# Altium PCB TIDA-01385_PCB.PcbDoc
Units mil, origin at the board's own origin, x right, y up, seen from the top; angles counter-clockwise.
Board outline 2300 x 1400 mil, 2 copper layers (Top Layer, Bottom Layer), stack 62 mil thick; 51 components, 23 nets, 141 pads, 23 vias.
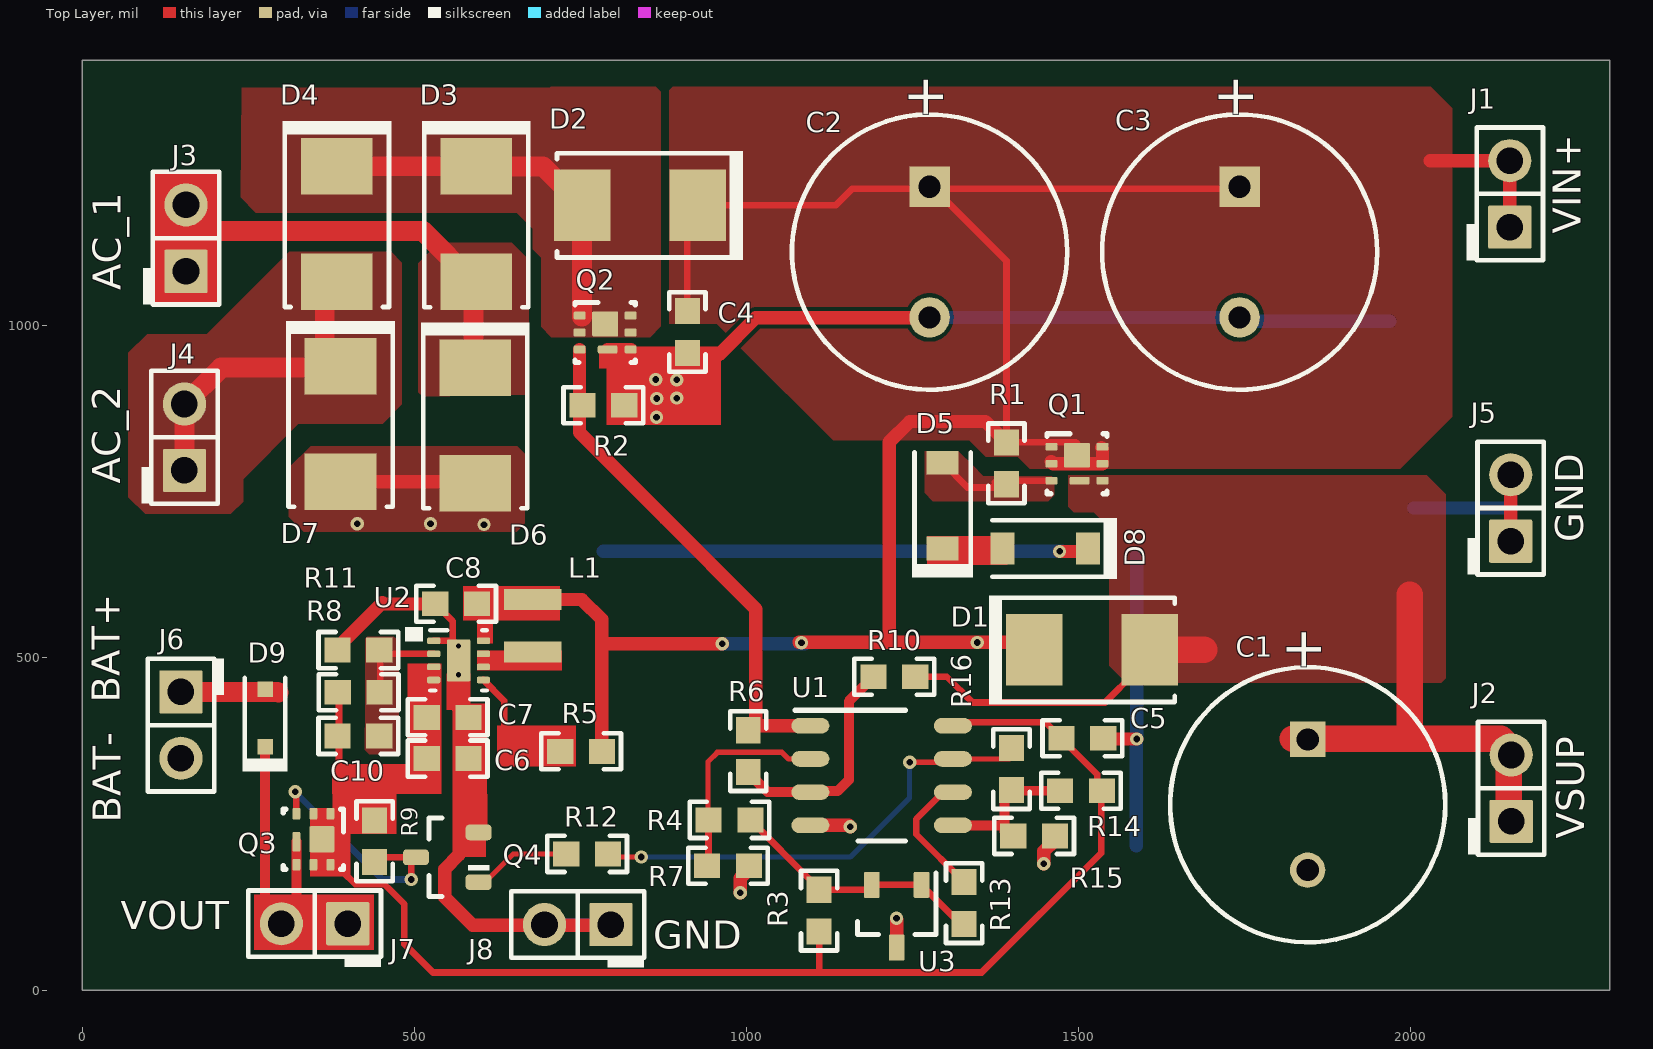
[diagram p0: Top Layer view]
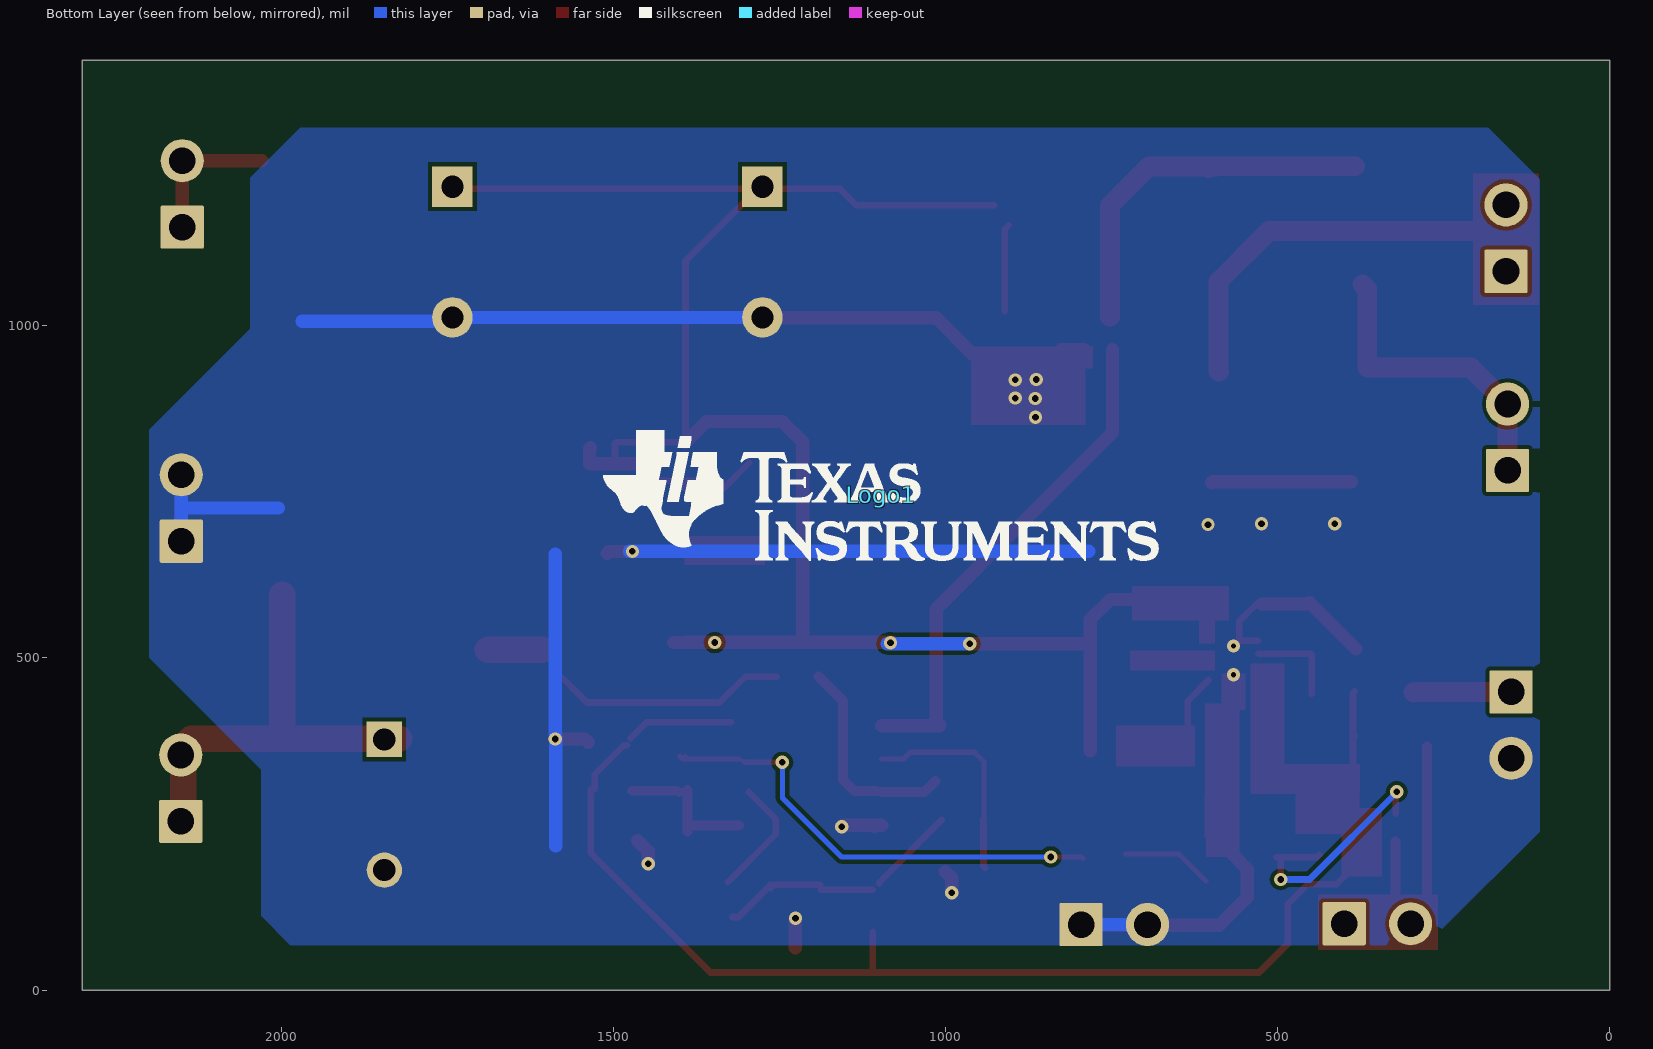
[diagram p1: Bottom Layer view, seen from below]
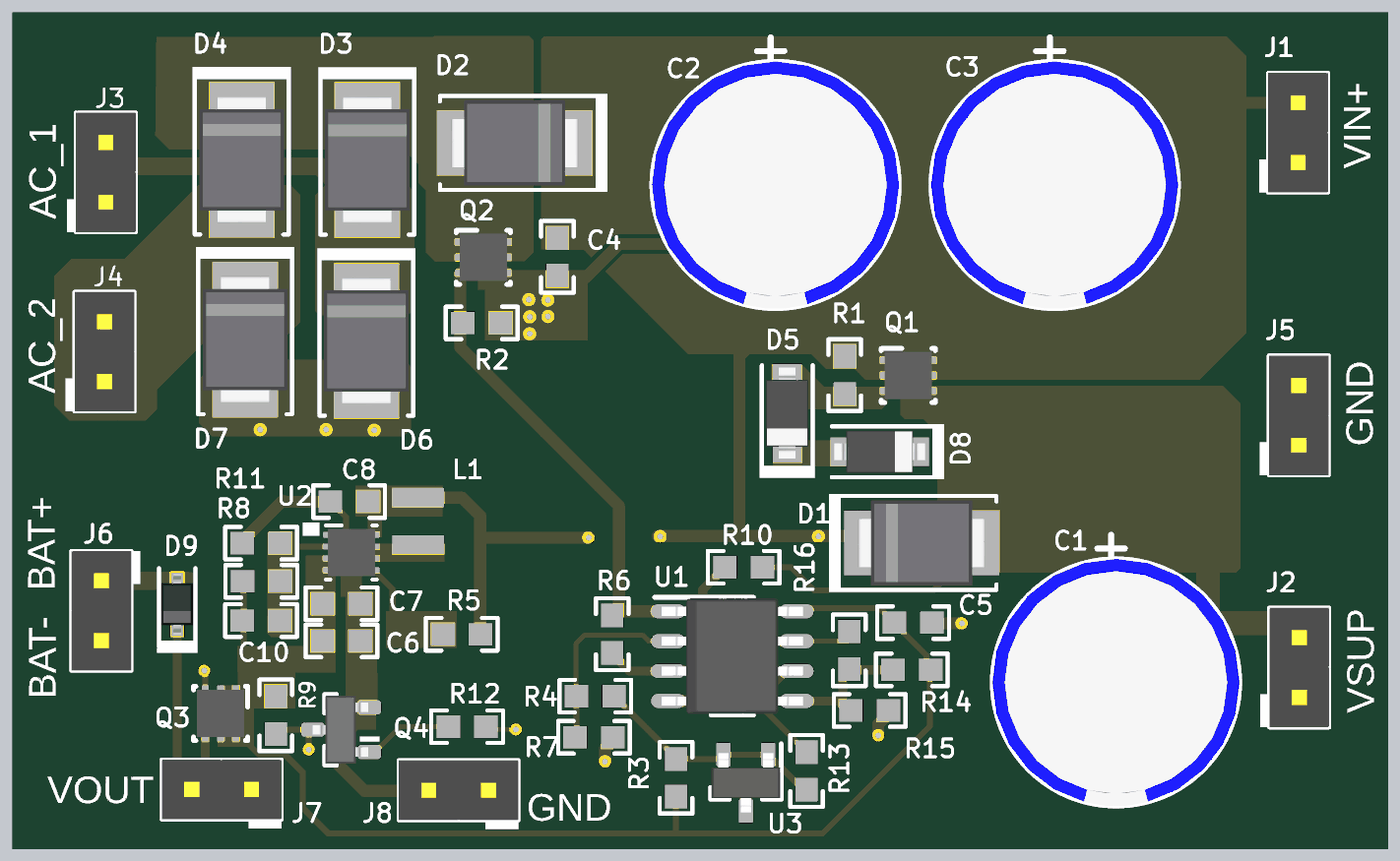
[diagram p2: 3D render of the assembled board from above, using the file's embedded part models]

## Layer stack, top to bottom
Top Solder: solder mask 0.4, Solder Resist, Dk 3.5
Top Layer: signal copper 1.4
Dielectric1: core 59.2, FR-4, Dk 4.8
Bottom Layer: signal copper 1.4
Bottom Solder: solder mask 0.4, Solder Resist, Dk 3.5

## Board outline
0,0 2300,0 2300,1400 0,1400

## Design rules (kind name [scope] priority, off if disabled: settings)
AcuteAngle [All] p1: minimum=4.50000000000000E+0001 checktracksonly=FALSE
AssemblyTestPointUsage [All] p1: valid=2
Clearance "U1 Clearance" [InComponent('Q1','Q2','Q3')] p1: gap=3.5
Clearance "U2 Clearance" [InComponent('U2')] p2: gap=4
Clearance Clearance_BoardEdge_MountingHoles [OnCopper and InComponentClass('Mounting Holes') vs IsKeepOut] p3: gap=3.94
Clearance Clearance_BoardEdge_Poly [OnCopper and InPoly vs IsKeepOut] p4: gap=10
Clearance Clearance_BoardEdge [OnCopper and Not InComponentClass('Logo') and not InComponentClass('FiducialMark') and not InRegion(1000,500,4000,800) vs IsKeepOut] p5: gap=30
Clearance [All] p6: gap=6
ComponentClearance ComponentClearance_SHUNT [InComponentClass('Shunt')] p1: gap=0 collisioncheckmode=3 verticalgap=0 showdistances=FALSE
ComponentClearance ComponentClearance_Logo [All] p2: gap=10 collisioncheckmode=3 verticalgap=10 showdistances=FALSE
ComponentClearance ComponentClearance_ScrewToNut [(HasFootprint('NY PMS 440 0025 PH')) vs (HasFootprint('Keystone_1902C'))] p3: gap=5 collisioncheckmode=3 verticalgap=10 showdistances=FALSE
ComponentClearance ComponentClearance_MountingHoles [InComponentClass('Mounting Holes')] p4: gap=250 collisioncheckmode=3 verticalgap=100000 showdistances=FALSE
ComponentClearance ComponentClearance_SmallPassives [HasFootprint('0201*') or HasFootprint('0402*') or HasFootprint('0508') or HasFootprint('0603*') or HasFootprint('0612') or HasFootprint('0805*') or HasFootprint('0815*') or HasFootprint('0830*') or HasFootprint('1206*') or HasFootprint('1210*') or HasFootprint('1808*') or HasFootprint('1812*') or HasFootprint('1825*') or HasFootprint('2010*') or HasFootprint('2220*') or HasFootprint('2225*') or HasFootprint('2512*') or HasFootprint('2728*') or HasFootprint('3518*') vs HasFootprint('0201*') or HasFootprint('0402*') or HasFootprint('0508') or HasFootprint('0603*') or HasFootprint('0612') or HasFootprint('0805*') or HasFootprint('0815*') or HasFootprint('0830*') or HasFootprint('1206*') or HasFootprint('1210*') or HasFootprint('1808*') or HasFootprint('1812*') or HasFootprint('1825*') or HasFootprint('2010*') or HasFootprint('2220*') or HasFootprint('2225*') or HasFootprint('2512*') or HasFootprint('2728*') or HasFootprint('3518*')] p5: gap=20 collisioncheckmode=3 verticalgap=10 showdistances=FALSE
ComponentClearance ComponentClearance_THtoSMT [IsThruComponent vs IsSMTComponent] p6 off: gap=10 collisioncheckmode=3 verticalgap=100000 showdistances=FALSE
ComponentClearance ComponentClearance_THtoTH [IsThruComponent vs IsThruComponent] p7: gap=10.11 collisioncheckmode=3 verticalgap=100000 showdistances=FALSE
ComponentClearance [All] p8: gap=10 collisioncheckmode=3 verticalgap=10 showdistances=FALSE
DiffPairsRouting [All] p1: maxlimit=100 minlimit=10 mostfreqgap=10 toplayer_minwidth=15 toplayer_maxwidth=15 toplayer_prefwidth=15 bottomlayer_minwidth=15 bottomlayer_maxwidth=15 bottomlayer_prefwidth=15 maxuncoupledlength=1000
FabricationTestPointUsage TestPointUsage [All] p1: valid=2 allowmultiple=FALSE
FabricationTestpoint Testpoint [All] p1: side=3 testpointundercomponent=TRUE minsize=40 maxsize=100 preferedsize=60 minholesize=0 maxholesize=40 preferedholesize=32 testpointgrid=1 allowsidetop=TRUE allowsidebottom=TRUE usegrid=TRUE gridtolerance=0.01
FanoutControl Fanout_LCC [IsLCC] p1: bgadir=Out bgaviamode=Centered fanoutstyle=Auto fanoutdirection=Alternating viagrid=1 // Fanout_LCC (Default Rule)
FanoutControl Fanout_BGA [IsBGA] p2: bgadir=Out bgaviamode=Centered fanoutstyle=Auto fanoutdirection=Alternating viagrid=1 // Fanout_BGA (Default Rule)
FanoutControl Fanout_Default [All] p4: bgadir=Out bgaviamode=Centered fanoutstyle=Auto fanoutdirection=Alternating viagrid=1 // Fanout_Default (Default Rule)
FanoutControl Fanout_Small [(CompPinCount < 5)] p5: bgadir=Out bgaviamode=Centered fanoutstyle=Auto fanoutdirection=OutThenIn viagrid=1 // Fanout_Small (Default Rule)
HoleSize [All] p1: absolutevalues=TRUE maxlimit=180 minlimit=7 maxpercent=80.000 minpercent=20.000
HoleToHoleClearance [All] p1: gap=1 allowstackedmicrovias=TRUE
MinimumAnnularRing MinimumAnnularRing_small [TouchesRoom('BGA_Room')] p1: minimumring=2.8
MinimumAnnularRing [All] p2: minimumring=5
MinimumSolderMaskSliver U2 [InComponent('U1')] p1: minsoldermaskwidth=3
MinimumSolderMaskSliver "SW PIN" [InNet('SW')] p2: minsoldermaskwidth=10
MinimumSolderMaskSliver U1 [InComponent('U2')] p3: minsoldermaskwidth=3
MinimumSolderMaskSliver SilkscreenOverComponentPads [All] p4: minsoldermaskwidth=5
MinimumSolderMaskSliver MinimumSolderMaskSliver_Logo [InComponentClass('Logo') vs InComponentClass('Logo')] p5: minsoldermaskwidth=0.7
MinimumSolderMaskSliver [All] p6: minsoldermaskwidth=4
PlaneClearance [All] p1: clearance=10
PlaneConnect [All] p1: planeconnectstyle=Direct reliefexpansion=10 reliefentries=4 reliefconductorwidth=10 reliefairgap=10
PolygonConnect PolygonConnect-TH-Relief [IsPoly vs (IsThruPin)  And Not (InComponent('U3'))  And Not (InComponent('U4'))] p1: connectstyle=Direct reliefconductorwidth=20 reliefentries=4 polygonreliefangle="90 Angle" airgapwidth=10
PolygonConnect PolygonConnect-DirectConn [All] p2: connectstyle=Direct reliefconductorwidth=10 reliefentries=4 polygonreliefangle="90 Angle" airgapwidth=10
RoutingVias [All] p1: holewidth=10 width=22 viastyle="Through Hole" minholewidth=4 minwidth=10 maxholewidth=50 maxwidth=100
SMDToCorner [All] p1: distance=0
SilkToBoardRegionClearance [Not ((IsComment or IsDesignator) And (Hide <> 'False')) and not InRegion(1000,500,4000,800)] p1:
SilkToSilkClearance "Pb Free Logo" [(HasFootprint('Pb-Free_Overlay_Medium') OR HasFootprint('Pb-Free_Overlay_Small')) vs (HasFootprint('Pb-Free_Overlay_Medium') OR HasFootprint('Pb-Free_Overlay_Small'))] p1: silktosilkclearance=0
SilkToSilkClearance [All] p2: silktosilkclearance=3
SilkToSolderMaskClearance [IsPad] p1: minsilkscreentomaskgap=4 clearancetoexposedcopper=TRUE
SolderMaskExpansion [All] p1: expansion=1
Width [All] p1: maxlimit=100 minlimit=6 preferedwidth=10 checkconnectedcopper=TRUE
13 further rules are at their usual default settings.

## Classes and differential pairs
component class Header: J1 J2 J3 J4 J5 J6 J7 J8
component class Logo: Logo1

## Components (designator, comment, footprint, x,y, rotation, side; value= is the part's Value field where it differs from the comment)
C1 "100ZL100MEFC10X23" ZL_1000x2300 1845.13,278.98 r270 top
C2 "ECA-2AHG101" NHG_1000x2000 1275.87,1111.17 r270 top
C3 "ECA-2AHG101" NHG_1000x2000 1742.66,1111.17 r270 top
C4 "GRM188R60J106ME47D" 0603 911.12,990.87 r270 top
C5 "GRM185R60J105KE26D" 0603 1505.93,378.99 r0 top
C6 "GRM188R60J226MEA0D" 0603 550.15,348.41 r0 top
C7 "GRM188R60J226MEA0D" 0603 550.15,410.56 r0 top
C8 "GRM188R60J106ME47D" 0603 563,581.61 r180 top
C10 "GRM188R61A224KA01D" 0603 415.75,382.5 r0 top
D1 "SL22-E3/52T" SMB 1520.21,512.3 r0 top
D2 "SL22-E3/52T" SMB 839.83,1181.45 r180 top
D3 "SL22-E3/52T" SMB 593.31,1153.1 r270 top
D4 "SL22-E3/52T" SMB 383.4,1153.35 r270 top
D5 "1N4148W-7-F" SOD-123 1295.58,729.38 r90 top
D6 "SL22-E3/52T" SMB 591.84,850.24 r270 top
D7 "SL22-E3/52T" SMB 389.01,852.47 r270 top
D8 "1N4148W-7-F" SOD-123 1450,664.81 r180 top
D9 "BAT54WS-7-F" SOD-323 275.45,409.8 r90 top
J1 "TSW-102-07-G-S" TSW-102-07-G-S#1 2149.42,1198.71 r90 top
J2 "TSW-102-07-G-S" TSW-102-07-G-S#1 2151.54,303.9 r90 top
J3 "TSW-102-07-G-S" TSW-102-07-G-S#2 144.05,1132.74 r90 top
J4 "TSW-102-07-G-S" TSW-102-07-G-S#1 153.97,832.32 r90 top
J5 "TSW-102-07-G-S" TSW-102-07-G-S#1 2150.81,725.76 r90 top
J6 "TSW-102-07-G-S" TSW-102-07-G-S#1 148.68,398.93 r270 top
J7 "TSW-102-07-G-S" TSW-102-07-G-S#1 349.88,99.88 r180 top
J8 "TSW-102-07-G-S" TSW-102-07-G-S#1 746.07,98.57 r180 top
L1 "74479887247" WE-PMI_1008 678.44,548.61 r270 top
Logo1 "Texas Instruments" TI_Stacked_Overlay_Small 1097.29,744.79 r180 bottom
Q1 "CSD25310Q2" DQK0006C 1497.87,792.44 r0 top
Q2 "CSD13202Q2" DQK0006C 787.25,990.02 r0 top
Q3 "CSD25310Q2" DQK0006C 348.08,227.07 r270 top
Q4 "MMBT3904" SOT-23 549.58,199.92 r180 top
R1 "CRCW0603200KFKEA" 0603 1391.57,793.07 r270 top
R2 "RC0603FR-07511KL" 0603 784.6,880.42 r180 top
R3 "CRCW060324K9FKEA" 0603 1109.48,119.45 r270 top
R4 "CRCW0603523KFKEA" 0603 974.48,256.03 r0 top
R5 "CRCW0603200KFKEA" 0603 751.15,359.41 r0 top
R6 "CRCW06031M00FKEA" 0603 1002.88,359.69 r90 top
R7 "CRCW06032M00FKEA" 0603 972.35,187.15 r180 top
R8 "CRCW06031M00FKEA" 0603 416.18,448.3 r180 top
R9 "CRCW06032M00FKEA" 0603 440.34,224.03 r90 top
R10 "RC0603FR-0769K8L" 0603 1222.66,471.77 r180 top
R11 "CRCW0603287KFKEA" 0603 415.82,511.89 r0 top
R12 "CRCW06032M00FKEA" 0603 760.2,204.93 r0 top
R13 "CRCW06031M00FKEA" 0603 1327.81,130.92 r90 top
R14 "CRCW06031M00FKEA" 0603 1503.81,300.04 r180 top
R15 "CRCW06037M50FKEA" 0603 1433.3,232.09 r180 top
R16 "CRCW06035M90FKEA" 0603 1399.23,332.67 r90 top
U1 "TLV3492AIDR" D0008A_N 1203.63,322.99 r0 top
U2 "TPS61021ADSGR" DSG0008A 566.67,496.32 r0 top
U3 "ATL431AIDBZR" DBZ0003A_N 1226.3,111.1 r270 top

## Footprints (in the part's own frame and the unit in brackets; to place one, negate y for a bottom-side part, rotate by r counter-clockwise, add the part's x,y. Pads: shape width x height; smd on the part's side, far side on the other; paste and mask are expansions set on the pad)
0603 [mm] "0603 from SM-752 data"
  rect 1x0.95 smd: 1(-0.8,0) 2(0.8,0)
  silkscreen extent -1.52,-0.69 1.52,0.69, body extent -0.87,-0.47 0.87,0.47, height 1
D0008A_N [mm] "SOIC, 8-Leads, Body 4.9x3.9mm, Pitch 1.27mm, IPC Medium Density"
  oval 1.45x0.6 smd: 1(-2.725,1.905) 2(-2.725,0.635) 3(-2.725,-0.635) 4(-2.725,-1.905) 5(2.725,-1.905) 6(2.725,-0.635) 7(2.725,0.635) 8(2.725,1.905)
  silkscreen extent -3.3,-2.5 0.9,2.5, body extent -3,-2.45 3,2.45, height 1.63
DBZ0003A_N [mm] "SOT23, 3-Leads, Body 2.9x1.3mm, Pitch 0.95mm, Lead Span 2.4mm, IPC Medium Density"
  rrect17% 1x0.6 smd: 1(-1.2,0.95) 2(-1.2,-0.95) 3(1.2,0)
  silkscreen extent -1.65,-1.5 0.7,1.5, body extent -1.26,-1.46 1.26,1.46, height 0.98
DQK0006C [mm] "WSON"
  rrect12% 0.9x0.86 on Top Paste: 0(0,0.325)
  rrect34% 0.7x0.29 on Top Paste: 0(0.095,-0.65)
  rrect33% 0.45x0.3 smd: 1(-0.975,0.65) 2(-0.975,0) 3(-0.975,-0.65) 4(0.975,-0.65) 5(0.975,0) 6(0.975,0.65)
  rrect33% 0.75x0.3 smd paste-0.15: 7(0.095,-0.65)
  rrect11% 1x0.95 smd paste-0.5: 8(0,0.325)
  silkscreen extent -1.15,-1.15 1.15,1.15, body extent -1,-1 1,1, height 0.82
DSG0008A [mm] "SON, 8-Leads, Body 2x2mm, Pitch 0.5mm, Thermal Pad 1.6x0.9mm, TI Recommended"
  rrect40% 0.5x0.25 smd: 1(-0.95,0.75) 2(-0.95,0.25) 3(-0.95,-0.25) 4(-0.95,-0.75) 5(0.95,-0.75) 6(0.95,-0.25) 7(0.95,0.25) 8(0.95,0.75)
  rrect14% 0.9x0.7 on Top Paste: 9(0,-0.45) 9(0,0.45)
  rrect11% 0.9x1.6 smd paste-0.45: 9(0,0)
  silkscreen extent -1.07,-1.15 1.07,1.15, body extent -1,-1 1,1, height 0.77
NHG_1000x2000 [mm] "PANASONIC"
  rect 1.55x1.55 hole 0.85: 1(-2.5,0)
  round 1.55 hole 0.85: 2(2.5,0)
  silkscreen extent -5.26,-5.26 5.26,5.26, body extent -5.21,-5.24 5.24,5.24, height 22.01
SMB [mil] "Molded Diode, 2-Leads, Body 5.4x3.6mm, IPC Medium Density, based on OnSemi component dimensions"
  rect 85x107.99 smd: 1(-87.01,0) 2(87.01,0)
  silkscreen extent -155,-82 125,82, body extent -106,-71 106,71, height 91
SOD-123 [mm] "On Semi recommended land pattern"
  rect 0.915x1.22 smd: 1(-1.637,0) 2(1.637,0)
  silkscreen extent -2.74,-1.17 2.03,1.17, body extent -1.93,-0.9 1.93,0.9, height 1.35
SOD-323 [mm] "NXP recommended land pattern"
  rect 0.6x0.6 smd paste-0.05: 1(-1.1,0) 2(1.1,0)
  silkscreen extent -2.06,-0.86 1.53,0.86, body extent -1.3,-0.67 1.3,0.68, height 1.1
SOT-23 [mm] "SOT23, 3-Leads, Body 2.9x1.3mm, Pitch 0.95mm, Lead Span 2.5mm, IPC Medium Density"
  rrect50% 1x0.6 smd: 1(-1.2,0.95) 2(-1.2,-0.95) 3(1.2,0)
  silkscreen extent -1.63,-1.5 0.7,1.5, body extent -1.16,-1.45 1.21,1.45, height 1
TI_Stacked_Overlay_Small [mil]
  silkscreen extent -418,-98 418,98
TSW-102-07-G-S#1 [mm] "Samtec 100mil, 1x2, 230 mil above insulator"
  rrect6% 1.65x1.65 hole 1.016: 1(-1.27,0)
  round 1.65 hole 1.016: 2(1.27,0)
  silkscreen extent -2.54,-1.27 2.54,1.65, body extent -2.54,-1.27 2.54,1.27, height 8.38
TSW-102-07-G-S#2 [mm] "Samtec 100mil, 1x2, 230 mil above insulator"
  rrect6% 1.65x1.65 hole 1.016: 1(-1.285,-0.311)
  round 1.65 hole 1.016: 2(1.255,-0.311)
  silkscreen extent -2.55,-1.58 2.53,1.34, body extent -2.55,-1.58 2.53,0.96, height 8.38
WE-PMI_1008 [mm] "WURTH"
  rect 0.8x2.2 smd: 1(-1,0) 2(1,0)
  body extent -1.35,-1.1 1.35,1.1, height 1
ZL_1000x2300 [mm] "RUBYCON"
  rect 1.35x1.35 hole 0.85: 1(-2.5,0)
  round 1.35 hole 0.85: 2(2.5,0)
  silkscreen extent -5.26,-5.26 5.26,5.26, body extent -5.21,-5.24 5.24,5.24, height 25.01

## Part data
C1: "CAP, AL, 100 µF, 100 V, +/- 20%, 0.12 ohm, TH"
C2 C3: "CAP, AL, 100 µF, 100 V, +/- 20%, TH"
C4 C8: "CAP, CERM, 10 µF, 6.3 V, +/- 20%, X5R, 0603"
C5: "CAP, CERM, 1 µF, 6.3 V, +/- 10%, X5R, 0603"
C6 C7: "CAP, CERM, 22 µF, 6.3 V, +/- 20%, X5R, 0603"
C10: "CAP, CERM, 0.22 µF, 10 V, +/- 10%, X5R, 0603"
D1 D2 D3 D4 D6 D7: "Diode, Schottky, 20 V, 2 A, SMB"
D5 D8: "Diode, Ultrafast, 100 V, 0.15 A, SOD-123"
D9: "Diode, Schottky, 30 V, 0.2 A, SOD-323"
J1 J2 J3 J4 J5 J6 J7 J8: "Header, 100mil, 2x1, Gold, TH"
L1: "Inductor, Shielded Drum Core, Metal Composite, 4.7 µH, 0.75 A, 0.53 ohm, SMD"
Logo1: library part TI_Logo, "Texas Instrument Corporate Signature"
Q1 Q3: "MOSFET, P-CH, -20 V, -20 A, DQK0006C (WSON-6)"
Q2: "MOSFET, N-CH, 12 V, 22 A, DQK0006C (WSON-6)"
Q4: library part "MMBT3904, Fairchild Semiconductor", "Transistor, NPN, 40 V, 0.2 A, SOT-23"
R1 R5: "RES, 200 k, 1%, 0.1 W, 0603"
R2: "RES, 511 k, 1%, 0.1 W, 0603"
R3: "RES, 24.9 k, 1%, 0.1 W, 0603"
R4: "RES, 523 k, 1%, 0.1 W, 0603"
R6 R8 R13 R14: "RES, 1.00 M, 1%, 0.1 W, 0603"
R7 R9 R12: "RES, 2.00 M, 1%, 0.1 W, 0603"
R10: "RES, 69.8 k, 1%, 0.1 W, 0603"
R11: "RES, 287 k, 1%, 0.1 W, 0603"
R15: "RES, 7.50 M, 1%, 0.1 W, 0603"
R16: "RES, 5.90 M, 1%, 0.1 W, 0603"
U1: "1.8V, Nanopower, PUSH-PULL OUTPUT COMPARATOR, D0008A (SOIC-8)"
U2: "3-A BOOST CONVERTER WITH 0.5V ULTRA-LOW INPUT VOLTAGE, DSG0008A (WSON-8)"
U3: "2.5V Low Iq Adjustable Precision Shunt Regulator, DBZ0003A (SOP-3)"

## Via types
v1: diameter 20, hole 10, Top Layer to Bottom Layer, 21 vias
v2: diameter 19.68, hole 7.87, Top Layer to Bottom Layer, 2 vias

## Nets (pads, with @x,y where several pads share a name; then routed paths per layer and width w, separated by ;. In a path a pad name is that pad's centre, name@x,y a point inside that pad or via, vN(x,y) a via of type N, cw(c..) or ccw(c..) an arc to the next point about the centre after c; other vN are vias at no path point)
GND: C1.2 C2.2 C3.2 C4.2 C5.2 C6.2 C7.2 C8.2 D6.2 D7.2 D8.1 J5.1 J5.2 J6.2 J8.1 J8.2 Q2.4 Q2.7 Q4.2 R2.1 R7.1 R11.1 R15.1 U1.4 U2.1 U2.9@566.67,496.32 U3.3 | length 4233
  Top Layer w10: U2.1 U2.9@557.67,525.84 ; C8.2 557.67,555.44 U2.9@557.67,525.84 ; U2.9@558.54,526.5 557.89,525.84 U2.9@557.67,525.84
  Top Layer w20: R11.1@382.33,513.83 451.56,583.06 ; D7.2 597.93,765.46 D6.2@599.75,763.64 ; 453.55,581.12 C8.2@523.94,581.12 ; v2(566.67,474.66) 566.67,422.89 C7.2@567.29,422.27 ; C7.2@567.29,428.35 C7.2@567.29,422.27 ; Q2.7 825.75,964.43 Q2.4@826.54,963.64 ; J8.1@805.13,97.47 588.2,97.47 545.91,139.76 545.91,182.05 567.29,203.44 C7.2@567.29,422.27 ; R2.1 816.09,955.98 958.06,955.98 1014.32,1012.24 C2.2@1279.07,1012.24 ; v1(990.81,146.33) 990.81,168.69 R7.1@1000.4,178.28 ; U1.4 1154.09,247.99 v1@1156.33,245.75 ; U1.4@1107.41,246.54 U1.4@1108.67,247.8 ; U3.3 v1@1226.3,105.77 ; v1(1447.67,189.94) 1447.67,208.81 R15.1@1464.02,225.16 ; v1(1471.58,660.41) 1506.82,660.41 D8.1@1509.46,657.77 ; C5.2@1538.21,373.24 1542.84,377.87 v1(1587.61,377.87) ; J5.1 J5.2 J5.2@2150.81,779.5
  Bottom Layer w20: J8.2@700.23,98.57 J8.1 ; 784.3,660.72 v1@1476.07,660.72 ; C2.2 1731.95,1012.74 1737.94,1006.75 1968.92,1006.75 ; 1586.8,216.96 v1@1586.8,379.32 ; v1(1587.61,377.87) 1587.61,656.23 ; 2004.83,725.76 2150.81,725.76 ; J5.1 2150.81,725.76 ; J5.2@2150.81,761.89 2150.81,725.76
  other v1: 1226.07,108.07 1156.33,246.06 604.89,700.79 414.23,701.89 524.38,701.89 864.75,862.22 864.97,890.55 895.36,891.24 863.38,919.33 895.13,918.65
  other v2: 566.67,517.97
NetC10_2: C10.2 R8.1 R11.2 U2.2 | length 140.4
  Top Layer w10: R8.1@448.83,445.89 448.83,505.67 449.32,506.16 U2.2
NetD2_2: D2.2 D3.1 D4.1 Q2.1 Q2.2 Q2.5 Q2.6 Q2.8 | length 564.5
  Top Layer w30: D4.1 601.75,1240.35 D3.1@601.99,1240.11 ; D3.1 D3.1@601.99,1240.11 ; D3.1@604.6,1237.5 D3.1@601.99,1240.11 ; D2.2@746.08,1188.08 694.05,1240.11 D3.1@601.99,1240.11 ; Q2.1@752.82,1013.69 D2.2
NetD5_1: D5.1 D8.2 | length 80.4
  Top Layer w10: D5.1 1375.64,664.92 D8.2@1375.87,664.69
NetD5_2: D5.2 Q1.3 R1.2 | length 203.4
  Top Layer w10: D5.2 1332.69,756.74 R1.2@1397.19,756.74 ; R1.2@1374.05,764.37 1376.53,766.85 Q1.3
NetD9_2: D9.2 J6.1 | length 147.1
  Top Layer w30: J6.1 294.37,448.93 295.36,447.94
NetL1_2: L1.2 U2.6 U2.7 | length 20.1
  Top Layer w10: U2.6@602.37,486.74 604.08,488.45 U2.7
NetQ3_3: Q3.3 Q4.3 R9.1 | length 359
  Top Layer w10: Q3.3 v1@322.49,296 ; R9.1@437.48,203.39 440.96,199.92 Q4.3 ; v1(495.38,166.54) 495.38,197.8 Q4.3@496.74,199.16
  Bottom Layer w10: v1@320.71,297.71 451.89,166.54 v1(495.38,166.54)
  other v1: 320.71,298.64
NetQ4_1: Q4.1 R12.1 | length 137.2
  Top Layer w8: Q4.1@608.33,164.25 649.01,204.93 R12.1
NetR3_1: R3.1 R4.2 R13.1 U3.1 U3.2 | length 367.2
  Top Layer w10: R4.2 1099.8,162.2 R3.1@1099.8,160.17 ; R3.1 U3.2@1188.2,150.94 ; U3.2 1258.4,158.34 U3.1@1263.3,153.44 ; U3.1 1312.05,109.99 R13.1@1321,109.99
NetR4_1: R4.1 R7.2 U1.2 | length 326.4
  Top Layer w8: R4.1@942.17,254.61 942.17,343.72 956.34,357.88 1053.69,357.88 1063.58,347.99 U1.2
  Top Layer w10: R7.2@940.4,183.96 942.98,186.54 R4.1
NetR5_1: R5.1 U2.5 | length 210.1
  Top Layer w10: U2.5 635.54,435.33 635.54,367.29 722.3,367.29 R5.1@729.96,359.64
NetR6_1: R6.1 R10.2 U1.3 | length 314.9
  Top Layer w15: R6.1@1015.59,314.47 1032.07,297.99 U1.3 ; U1.3@1104.58,299.44 1137.19,299.44 1154.2,316.45 1154.2,434.8 R10.2
NetR13_2: R13.2 U1.6 | length 182.5
  Top Layer w10: U1.6@1296.52,298.15 1255.71,257.34 1255.71,234.52 R13.2
NetR14_2: R14.2 R15.2 R16.1 U1.5 | length 215.2
  Top Layer w10: R16.1@1397.37,299.31 R16.1@1401.06,295.63
  Top Layer w15: U1.5 1382.7,247.99 1388.53,253.82 ; R15.2@1388.53,238.61 1388.53,253.82 ; R16.1@1388.55,301.26 1388.55,301.18 1388.53,253.82 ; R16.1@1405.08,300.04 R14.2
NMOS_DRI: Q2.3 R2.2 R6.2 U1.1 | length 1052.9
  Top Layer w10: Q2.3@753.1,963.19 R2.2 753.1,836.38 868.22,721.26
  Top Layer w20: Q2.3 748.86,839.33 877.12,711.08 ; 877.83,710.13 1014.24,573.73 R6.2@1014.24,397.99 ; R6.2@1008.56,398.75 1009.32,397.99 R6.2@1014.24,397.99 ; U1.1 R6.2@1014.24,397.99
PMOS_DRI: R12.2 R16.2 U1.7 | length 696
  Top Layer w8: R12.2@793.52,198.26 795.61,200.34 v1(841.8,200.34) ; v1(1245.87,342.8) 1302.67,342.8 U1.7@1303.94,344.07 ; U1.7 1396.28,347.99 R16.2@1400.5,352.21
  Top Layer w10: R16.2@1391.79,350.52 R16.2@1392.43,349.88
  Bottom Layer w8: v1(841.8,200.34) 1156.66,200.34 1245.71,289.4 1245.71,344.07 v1@1245.36,344.42
V_3.6: C5.1 C6.1 C7.1 C10.1 Q3.1 Q3.2 Q3.5 Q3.6 Q3.8 R3.2 R8.2 R9.2 R14.1 U1.8 U2.3 U2.4 | length 2258.2
  Top Layer w10: Q3.5 Q3.6 374.86,188.68 Q3.6@375.5,189.32 ; Q3.2 Q3.1 444.33,265.46 R9.2@444.99,264.8 ; 382.29,182.4 386.99,182.4 ; R8.2@384.21,449.59 386.63,447.17 C10.1@386.63,382.5 ; C10.1 386.57,380.18 386.57,321.53 ; 388.41,334.65 504.9,334.65 C6.1 518.66,407.03 C7.1@523.44,411.82 ; 391.93,178.48 411.24,159.17 454.83,159.17 463.79,150.22 ; 459.94,154.24 485.12,129.07 485.12,69.34 528.13,26.32 1354.22,26.32 1534.3,206.39 R14.1@1534.3,301.97 ; C7.1@529.09,416.51 529.27,416.69 U2.4 U2.3 ; 1109.48,27.58 R3.2 ; U1.8@1322.51,403.15 1450.28,403.15 C5.1 ; C5.1@1479.75,368.56 1484.22,368.56 1528.31,324.47 R14.1@1528.31,302.41
VAC_1: D3.2 D6.1 J3.1 J3.2 | length 702.6
  Top Layer w30: J3.1 156.31,1142.54 ; J3.2@156.31,1184.56 J3.2 156.31,1142.54 ; D6.1@588.12,931.28 589.09,932.25 589.09,1066.95 513.51,1142.54 156.31,1142.54
VAC_2: D4.2 D7.1 J4.1 J4.2 | length 461.5
  Top Layer w30: J4.1 153.97,881.84 209.22,937.1 365.24,937.1 365.24,1055.32 D4.2@372.03,1062.11
VIN+: C2.1 C3.1 C4.1 C8.1 D1.1 D2.1 J1.1 J1.2 L1.1 Q1.1 Q1.2 Q1.5 Q1.6 Q1.8 R1.1 R5.2 U2.8 | length 3358.8
  Top Layer w10: U2.8 604.08,574.31 C8.1@606.16,576.4 ; D2.1@904.93,1151.42 911.12,1145.23 C4.1 ; D2.1 1134.44,1181.45 1159.58,1206.59 C3.1@1741.59,1206.59 ; C2.1@1294.54,1194.83 1391.57,1097.79 R1.1 1496.18,824.57 1497.87,822.88 Q1.8
  Top Layer w20: L1.1 752.3,587.98 782.13,558.14 R5.2@782.13,359.96 ; 785.34,521.26 v1(963.65,521.26) ; v1@1079.11,523.86 D1.1@1391.41,523.86 ; 1215.22,526.27 1215.22,825.14 1246.05,855.97 1360.17,855.97 R1.1 ; v1(1347.62,523.22) D1.1@1409.2,523.22 ; Q1.2@1458.94,795.74 1462.25,792.44 Q1.5 1536.26,815.27 Q1.6@1534.73,816.8 ; 2029.47,1248.71 J1.2 J1.1
  Bottom Layer w20: v1(963.65,521.26) v1@1088.13,521.26
  other v1: 1083.06,523.08
VOUT: D9.1 J7.1 J7.2 Q3.4 Q3.7 | length 593
  Top Layer w10: J7.2 J7.1 J7.1@411.62,99.88
  Top Layer w15: D9.1 275.45,129.4 J7.2@289.46,115.38 ; J7.2@322.49,102.46 322.49,103.56 Q3.7
  Top Layer w20: J7.2@300.89,103.56 322.49,103.56 J7.1@404.37,103.56
VSUP: C1.1 D1.2 J2.1 J2.2 Q1.4 Q1.7 R10.1 | length 1238.3
  Top Layer w10: R10.1 1301.76,471.77 1340.62,432.9 1539.87,432.9 D1.2@1586.23,479.25 ; D1.2@1607.22,498.15 D1.2 ; J2.1@2151.54,249.64 J2.1 J2.2 ; J2.2@2153.19,355.55 J2.2@2158.92,349.82
  Top Layer w40: D1.2 1689,512.3 ; C1.1@1822.98,378.32 1998.85,378.32 ; 1998.85,595.23 1998.85,378.32 ; J2.1@2147.75,250.52 2147.75,366.59 2136.03,378.32 1998.85,378.32
pads on no net: Q1.0 Q2.0 Q3.0 U2.9@566.67,478.6 U2.9@566.67,514.03

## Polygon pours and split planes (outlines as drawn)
VSUP on Top Layer "TOP_LAYER_VSUP_P038" (solid, remove dead copper, pour order 38): 1485,775.42 2024.28,775.42 2053.03,746.66 2053.03,469.75 2045.93,462.65 1571.62,462.65 1546.06,488.21 1546.06,696.25 1522.98,719.33 1489.26,719.33 1484.64,723.94
NetD2_2 on Top Layer "TOP_LAYER_NETD2_2_P000" (solid, remove dead copper, pour order 0): 240.6,1358.87 801.37,1358.87 824.83,1335.41 824.83,1130.23 810.39,1115.79 709.31,1115.79 654.56,1170.55 261.66,1170.55 238.8,1193.41
VAC_2 on Top Layer "TOP_LAYER_VAC_2_P002" (solid, remove dead copper, pour order 2): 313.83,1111.39 465,1111.39 481.47,1094.92 481.47,881.74 452.4,852.67 325.46,852.67 242.12,769.33 242.12,735.42 223.71,717.01 94.84,717.01 69.64,742.2 69.64,959.26 97.74,987.36 187.86,987.36 311.89,1111.39
VAC_1 on Top Layer "TOP_LAYER_VAC_1_P004" (solid, remove dead copper, pour order 4): 672.36,896.27 672.36,1099.86 646.78,1125.44 536.99,1125.44 521,1109.45 506.08,1094.53 506.08,893.07
GND on Top Layer "TOP_LAYER_GND_P006" (solid, remove dead copper, pour order 6): 311.36,751.98 311.36,786.33 343.96,818.93 654.92,818.93 666.37,807.48 666.37,702.65 654.04,690.31 333.39,690.31 311.36,712.34
NetD2_2 on Top Layer "TOP_LAYER_NETD2_2_P008" (solid, remove dead copper, pour order 8): 855.43,983.2 871.42,999.2 871.42,1106.14 871.42,1352.58 863.85,1360.16 705.49,1360.16 678.7,1333.38 678.7,1115.24 691.27,1102.67 691.27,998.31 706.58,982.99
VIN+ on Top Layer "TOP_LAYER_VIN+_P010" (solid, remove dead copper, pour order 10): 884.05,1003.4 884.05,1354.54 889.39,1359.87 2030.34,1359.87 2062.85,1327.36 2062.85,863.4 1984.64,785.18 1581.78,785.18 1426.44,785.18 1408.39,803.23 1360.26,803.23 1335.64,827.85 1130.48,827.85 956.11,1002.23
NetD5_2 on Top Layer "TOP_LAYER_NETD5_2_P012" (solid, remove dead copper, pour order 12): 1268.23,811.29 1319.19,811.29 1340.56,789.92 1356.59,773.9 1409.19,773.9 1459.73,773.9 1463.43,770.2 1463.43,745.13 1454.39,736.09 1280.56,736.09 1268.23,748.42
NetC10_2 on Top Layer "TOP_LAYER_NETC10_2_P030" (solid, remove dead copper, pour order 30): 426.2,428.67 426.2,528.93 429.33,532.06 471.58,532.06 476.85,526.79 476.79,526.73 476.79,452.65 476.79,357.86 472.73,353.79 471.87,354.65 425.22,354.65
GND on Bottom Layer "BOTTOM_LAYER_GND_P036" (solid, remove dead copper, pour order 36): 105.71,1114.74 105.71,1220.51 183.27,1298.08 1971.72,1298.08 2046.64,1223.16 2046.64,995.74 2199.13,843.25 2199.13,500.37 2070.44,371.68 2030.78,332.02 2030.78,111.65 1986.71,67.58 1835.1,67.58 276.71,67.58 105.71,238.58

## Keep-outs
Keep-Out Layer:
  text ".Layer_Name" at 577,-858.49 h60

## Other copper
Top Layer:
  rectangle net NetR5_1: 624.41,336.84 743.18,398.45
  rectangle net GND: 778.12,935.45 962.13,969.03
  rectangle net GND: 789.54,850.83 962.13,947.54
  rectangle net NetD5_1: 1271.6,640.15 1393.5,683.73
  rectangle net VAC_1: 106.94,1031.35 205.87,1229.58
  rectangle net V_3.6: 376.15,295.16 540.61,340.2
  rectangle net GND: 569.79,275.79 609.59,431.65
  rectangle net GND: 548.82,421.96 584.36,476.47
  rectangle net V_3.6: 490.05,327.41 540.61,491.58
  rectangle net NetL1_2: 594.22,481.06 722.45,511.03
  rectangle net VIN+: 573.61,556.03 719.28,608.03
  rectangle net VIN+: 594.08,521.5 618.19,560.21
  rectangle net VOUT: 258.32,60.43 439.7,143.65
  rectangle net V_3.6: 343.01,170.96 403.78,274.36
  rectangle net V_3.6: 402.3,235.11 473.41,274.36
  rectangle net V_3.6: 376.56,267.39 472.99,307.7
  rectangle net GND: 573.27,228.33 610.09,295
  rectangle net GND: 566.8,199.96 608.1,246.73
  text ".Layer_Name" at 577,-858.49 h60
Bottom Layer:
  text ".Layer_Name" at 577,-858.49 h60

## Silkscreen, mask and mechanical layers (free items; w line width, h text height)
Top Overlay:
  rectangle: 485.74,524.57 513.03,546.55
  text "VIN+" at 2270.65,1138.7 h72.83 r90
  text "AC_1" at 72.41,1053.87 h72.83 r90
  text "AC_2" at 71.33,762.3 h72.83 r90
  text "GND" at 2274.43,674.35 h72.83 r90
  text "BAT+" at 70.48,432.66 h72.83 r90
  text "BAT-" at 72.21,251.57 h72.83 r90
  text "VSUP" at 2276.05,227.82 h72.83 r90
  text "VOUT" at 58.18,77.18 h72.83
  text "GND" at 859.63,47.85 h72.83
  text ".Layer_Name" at 577,-858.49 h60
Bottom Overlay:
  text ".Layer_Name" at 577,-858.49 h60
Top Paste:
  text ".Layer_Name" at 577,-858.49 h60
Bottom Paste:
  text ".Layer_Name" at 577,-858.49 h60
Top Solder:
  text ".Layer_Name" at 577,-858.49 h60
  text ".Layer_Name" at 577,-858.49 h60
Bottom Solder:
  text ".Layer_Name" at 577,-858.49 h60
Drill Guide:
  text ".Layer_Name" at 577,-858.49 h60
M1 Board Outline:
  the board outline again, w4
  text ".Layer_Name" at 577,-858.49 h60
M2 Board Dimensions:
  rectangle: 125,-400 500,-275
  rectangle: 0,-275 125,-150
  lines w7: 0,-275 1000,-275 ; 125,-400 125,-150 ; 250,-400 250,-150 ; 500,-400 500,-150 ; 750,-400 750,-150 ; 0,-400 0,-150 1000,-150 1000,-400 0,-400
  text ".Layer_Name" at 577,-858.49 h60
M3 3D STEP Top:
  text ".Layer_Name" at 577,-858.49 h60
M4 3D STEP Bottom:
  text ".Layer_Name" at 577,-858.49 h60
M5 Assembly Top:
  lines w10: -292,-930.17 6308,-930.17 ; -292,-726.83 6310,-726.83 ; -292,-523.5 -292,-1133.5 3713,-1133.5 6310,-1133.5 6310,-523.5 -291.5,-523.5 -291.5,-1133.5 1284,-1133.5 ; 2173,-1133.5 2173,-523.5 ; 3440,-726.83 3440,-523.5 ; 4280,-726.83 4280,-523.5 ; 4902,-1140 4902,-937.17
  text "COMPONENTS MARKED 'DNP' SHOULD NOT BE POPULATED." at 1153.5,-318.5 h60
  text "ASSEMBLY VARIANT:" at 1153,-434 h60
  text ".VariantName" at 2189,-434 h60
  text "PCB VIEWED FROM TOP SIDE" at -228.5,-655.67 h60
  text "BOARD #:" at 2248,-655.67 h60
  text ".PRJ_Number" at 2793.5,-655.67 h60
  text "REV:" at 3638,-655.67 h60
  text ".PCB_Rev" at 3929.5,-655.67 h60
  text "SVN REV:" at 4476,-655.67 h60
  text ".VersionControl_RevNumber" at 4982,-655.67 h60
  text "TID #:" at 2248,-859 h60
  text ".TID" at 2793.5,-859 h60
  text "PLOT NAME =" at -228.5,-1064.34 h60
  text ".plot_File_Name" at 577,-1064.34 h60
  text "GENERATED    :" at 2250,-1064.34 h60
  text ".Print_Date" at 3119.5,-1064.34 h60
  text ".Print_Time" at 3848.5,-1064.34 h60
  text "TEXAS INSTRUMENTS" at 5113,-1064.34 h60
M6 Assembly Bottom:
  lines w10: -292.5,-727.33 6309.5,-727.33 ; -290.5,-930.67 6309.5,-930.67 ; 1115.5,-1140.5 1115.5,-937.67 ; 1737.5,-727.33 1737.5,-524 ; 2577.5,-727.33 2577.5,-524 ; 3844.5,-1134 3844.5,-524 ; 4733.5,-1134 6309,-1134 6309,-524 -292.5,-524 -292.5,-1134 2304.5,-1134 6309.5,-1134 6309.5,-524
  text "COMPONENTS MARKED 'DNP' SHOULD NOT BE POPULATED." at 6102,-318 h60
  text ".VariantName" at 5058,-434 h60
  text "ASSEMBLY VARIANT:" at 6097,-434 h60
  text ".VersionControl_RevNumber" at 1035.5,-656.17 h60
  text "SVN REV:" at 1541.5,-656.17 h60
  text ".PCB_Rev" at 2088,-656.17 h60
  text "REV:" at 2379.5,-656.17 h60
  text ".PRJ_Number" at 3224,-656.17 h60
  text "BOARD #:" at 3769.5,-656.17 h60
  text "PCB VIEWED FROM BOTTOM SIDE" at 6246,-656.17 h60
  text ".TID" at 3224,-859.5 h60
  text "TID #:" at 3769.5,-859.5 h60
  text "TEXAS INSTRUMENTS" at 904.5,-1064.84 h60
  text ".Print_Time" at 2169,-1064.84 h60
  text ".Print_Date" at 2898,-1064.84 h60
  text "GENERATED    :" at 3767.5,-1064.84 h60
  text ".plot_File_Name" at 5440.5,-1064.84 h60
  text "PLOT NAME =" at 6246,-1064.84 h60
M9 Title Sheet:
  drawing of 57 lines, arcs and shapes, not listed
  text "1" at 739.84,8036.5 h70
  text "2" at 3235.5,8036.5 h70
  text "3" at 5724.84,8036.5 h70
  text "4" at 8231.51,8036.5 h70
  text "5" at 10730.5,8036.5 h70
  text "6" at 13235.5,8036.5 h70
  text "A" at -416.5,6893.5 h70
  text "A" at 14383.5,6893.5 h70
  text "B" at -416.5,4513.5 h70
  text "B" at 14383.5,4513.5 h70
  text "C" at -416.5,2138.5 h70
  text "C" at 14383.5,2138.5 h70
  text "PROJECT TITLE:" at 11343.5,277.5 h45
  text ".PRJ_Title" at 11393.5,144.17 h70
  text "DESIGNED FOR:" at 11343.5,-23.5 h45
  text ".PRJ_Customer" at 11393.5,-163.5 h70
  text "D" at -416.5,-231.5 h70
  text "D" at 14383.5,-231.5 h70
  text "FILE NAME:" at 11343.5,-323.5 h45
  text ".PCB_File_Name_No_Path" at 11393.5,-443.5 h70
  text "Texas Instruments (TI) and/or its licensors do not warrant the accuracy or completeness of this specification" at 6374,-605.34 h45
  text "ENGINEER:" at 11343.5,-613.5 h45
  text "LAYOUT BY:" at 12848.5,-613.5 h45
  text "or any information contained therein. TI and/or its licensors do not warrant that this design will meet" at 6329.01,-718 h45
  text ".PRJ_Engineer" at 11393.5,-768.49 h70
  text ".PCB_Layout" at 12899,-768.49 h70
  text "the specifications, will be suitable for your application or fit for any particular purpose, or will operate in" at 6329.01,-830.67 h45
  text ".Layer_Name" at 577,-858.49 h60
  text "ALTIUM DESIGNER VERSION:" at 12848.5,-923.5 h45
  text "an implementation. TI and/or its licensors do not warrant that the design is production worthy. You should" at 6329.01,-943.33 h45
  text "completely validate and test your design implementation to confirm the system functionality for your application." at 6374,-1056 h45
  text ".print_Scale" at 11393.5,-1056.83 h70
  text ".Application_BuildNumber" at 12899,-1056.83 h70
  text "1" at 739.84,-1263.5 h70
  text "2" at 3235.5,-1263.5 h70
  text "3" at 5724.84,-1263.5 h70
  text "4" at 8231.51,-1263.5 h70
  text "5" at 10730.5,-1263.5 h70
  text "6" at 13235.5,-1263.5 h70
M10 Fab Notes:
  drawing of 173 lines, arcs and shapes, not listed
  text "DESIGN INFORMATION" at 12378.02,6201 h60
  text "MIN. TRACK WIDTH:" at 11733.46,6021 h60
  text "8" at 12829.7,6021 h60
  text "MIL" at 12984.46,6021 h60
  text "MIN. CLEARANCE:" at 11733.46,5889 h60
  text "0.2" at 12769.7,5889 h60
  text "mm" at 12984.46,5889 h60
  text "MIN. VIA PAD SIZE:" at 11733.46,5757 h60
  text "24" at 12799.71,5757 h60
  text "MIL" at 12984.46,5757 h60
  text "0.05mm (2MIL)" at 12428.46,5615.29 h60
  text "MINIMUM ANNULAR RING" at 11404.23,5611 h60
  text "EXTERNAL" at 13136.46,5611 h60
  text "PER" at 11604.23,5493 h60
  text "IPC-D-275 CLASS 2 LEVEL C" at 11824.23,5493 h60
  text "MIL, HOLES" at 13312.46,5380.71 h60
  text "+/-" at 12920,5380 h60
  text "+/-" at 13774,5380 h60
  text "REGISTRATION TOLERANCES:" at 11404.23,5375 h60
  text "METAL" at 12604,5375 h60
  text "5" at 13180.2,5375 h60
  text "3" at 14013.2,5375 h60
  text "MIL" at 14129.46,5375 h60
  text "+/-" at 13774,5262 h60
  text "HOLE SIZE TOLERANCE (UNLESS OTHERWISE SPECIFIED):" at 11404.23,5257 h60
  text "3" at 14013.2,5257 h60
  text "MIL" at 14129.46,5257 h60
  text "MATERIAL:" at 11329.46,5047.54 h60
  text "FR-4 High Tg" at 12315.9,4907.21 h60
  text "FR-408" at 11750.46,4898.64 h60
  text "OTHER" at 13238.46,4898.64 h60
  text "X" at 13051.11,4889.52 h60
  text "62 MIL (1.6mm) +/-10%" at 12070.56,4735.92 h60
  text "THICKNESS:" at 11404.23,4731.64 h60
  text "X" at 11942.4,4731.64 h60
  text "OTHER" at 13355.46,4731.64 h60
  text "TOLERANCE:" at 11404.23,4573.64 h60
  text "X" at 12243.53,4573.64 h60
  text "ANSI IPC-6012 TYPE 3 CLASS 2" at 12430.48,4573.64 h60
  text "OTHER +/-" at 12430.46,4417.64 h60
  text "BOW & TWIST:" at 11404.23,4260.64 h60
  text "X" at 12243.53,4260.64 h60
  text "ANSI IPC-6012 TYPE 3 CLASS 2" at 12430.48,4260.64 h60
  text "OTHER +/-" at 12430.46,4102.13 h60
  text "DRILLING:" at 11329.46,3963.64 h60
  text "REFERENCE:" at 11404.23,3846.64 h60
  text "X" at 12052.46,3846.64 h60
  text "AS SHOWN" at 12239.46,3846.64 h60
  text "X" at 12953.46,3846.64 h60
  text "NC_DRILL FILES" at 13090.46,3846.64 h60
  text "PTH COPPER THICKNESS:" at 11404.23,3688.64 h60
  text "X" at 12534.46,3688.64 h60
  text "20-30 um" at 12671.46,3688.64 h60
  text "OTHER" at 13388.46,3688.64 h60
  text "BOARD FINISH:" at 11329.46,3529.64 h60
  text "SILKSCREEN:" at 11484.68,3411.64 h60
  text "X" at 12433.46,3411.64 h60
  text "TOP" at 12559.46,3411.64 h60
  text "X" at 12943.46,3411.64 h60
  text "BOTTOM" at 13070.46,3411.64 h60
  text "SILKSCREEN COLOR:" at 11484.68,3244.64 h60
  text "X" at 12432.42,3244.64 h60
  text "WHITE" at 12559.46,3244.64 h60
  text "OTHER" at 13070.46,3244.64 h60
  text "X" at 12563.42,3085.44 h60
  text "GREEN" at 12690.46,3085.44 h60
  text "OTHER" at 13308.46,3085.44 h60
  text "SOLDER RESIST COLOR:" at 11484.68,3074.64 h60
  text "X" at 12563.42,2915.44 h60
  text "MATTE" at 12690.46,2915.44 h60
  text "SEMI-GLOSS" at 13308,2914.8 h60
  text "IMMERSION GOLD (ENIG)" at 12390.46,2726.92 h60
  text "ENEPIG" at 13728,2723.64 h60
  text "SURFACE FINISH:" at 11329.46,2722.64 h60
  text "IMM. TIN/SILVER OR EQUIV" at 11659,2565.64 h60
  text "OTHER" at 13090.46,2565.64 h60
  text "X" at 11493.42,2555.59 h60
  text "ARRAY/PANEL:" at 11329.46,2386.64 h60
  text "CUT AND TRIM PER M1 BOARD OUTLINE" at 12390.46,2382.35 h60
  text "N.C. ROUTE" at 12390.46,2230.64 h60
  text "X" at 13069.46,2230.64 h60
  text "V. SCORE" at 13256.46,2230.64 h60
  text "CERTIFICATION:" at 11329.46,2093.64 h60
  text "MATERIALS AND WORKMANSHIP FOR ALL PCBS" at 12054.46,2093.64 h60
  text "TO MEET OR EXCEED THE REQUIREMENTS OF:" at 12054.46,1995.64 h60
  text "X" at 11680.96,1859.13 h60
  text "ANSI IPC-A-600F CLASS ->" at 11819.96,1859.13 h60
  text "X" at 13459.02,1859.13 h60
  text "2" at 13577.96,1859.14 h60
  text "1" at 13262.96,1857.64 h60
  text "3" at 13931.96,1857.64 h60
  text "X" at 12495.02,1699.64 h60
  text "RoHS" at 12631.96,1699.64 h60
  text "OTHER" at 13276.36,1699.64 h60
  text "PER ORDER" at 13673.42,1699.64 h60
  text "ALL BOARDS MUST MEET OR EXCEED UL94-V0 REQUIREMENTS." at 11357,1534 h60
  text "PCB MUST BEAR THE UL94V-0 UL REGISTERED MATERIAL ID NUMBER" at 11357,1414 h60
  text "ADDITIONAL REQUIREMENTS:" at 11329.46,1240.64 h60
  text "MICROSECTION:" at 11404.23,1125.64 h60
  text "YES" at 12309.96,1125.64 h60
  text "REQUIRED" at 13171.46,969.49 h60
  text "BARE BOARD ELEC. TEST:" at 11404.23,966.64 h60
  text "NONE" at 12709.96,966.64 h60
  text "X" at 13044.46,966.64 h60
  text "PER ORDER" at 13763.46,966.64 h60
  text ".Layer_Name" at 577,-858.49 h60
M11 Gerber Information:
  lines w10: -292,-930.17 6308,-930.17 ; -292,-726.83 6310,-726.83 ; -292,-523.5 -292,-1133.5 3713,-1133.5 6310,-1133.5 6310,-523.5 -291.5,-523.5 -291.5,-1133.5 1284,-1133.5 ; 2173,-1133.5 2173,-523.5 ; 3440,-726.83 3440,-523.5 ; 4280,-726.83 4280,-523.5 ; 4902,-1140 4902,-937.17
  text "ALL ARTWORK VIEWED FROM TOP SIDE" at -228.5,-655.67 h60
  text "BOARD #:" at 2248,-655.67 h60
  text ".PRJ_Number" at 2793.5,-655.67 h60
  text "REV:" at 3638,-655.67 h60
  text ".PCB_Rev" at 3929.5,-655.67 h60
  text "SVN REV:" at 4476,-655.67 h60
  text ".VersionControl_RevNumber" at 4982,-655.67 h60
  text "LAYER NAME =" at -228.5,-858.49 h60
  text "TID #:" at 2248,-859 h60
  text ".TID" at 2793.5,-859 h60
  text "PLOT NAME =" at -228.5,-1064.34 h60
  text ".plot_File_Name" at 577,-1064.34 h60
  text "GENERATED    :" at 2250,-1064.34 h60
  text ".Print_Date" at 3119.5,-1064.34 h60
  text ".Print_Time" at 3848.5,-1064.34 h60
  text "TEXAS INSTRUMENTS" at 5113,-1064.34 h60
M12 Stackup:
  drawing of 191 lines, arcs and shapes, not listed
  text "Layer" at 9790.34,7830 h60
  text "Name" at 10200.26,7830 h60
  text "Material" at 11130,7830 h60
  text "Thickness" at 11989.77,7830 h60
  text "Constant" at 12639.6,7830 h60
  text "Board Layer Stack" at 13209.46,7830 h60
  text "1" at 9790.34,7710 h60
  text "Top Overlay" at 10200.26,7710 h60
  text "2" at 9790.34,7590 h60
  text "Top Solder" at 10200.26,7590 h60
  text "Solder Resist" at 11130,7590 h60
  text "0.40mil" at 11989.77,7590 h60
  text "3.5" at 12639.6,7590 h60
  text "3" at 9790.34,7470 h60
  text "Top Layer" at 10200.26,7470 h60
  text "Copper" at 11130,7470 h60
  text "1.40mil" at 11989.77,7470 h60
  text "4" at 9790.34,7350 h60
  text "Dielectric1" at 10200.26,7350 h60
  text "FR-4" at 11130,7350 h60
  text "59.20mil" at 11989.77,7350 h60
  text "4.8" at 12639.6,7350 h60
  text "5" at 9790.34,7230 h60
  text "Bottom Layer" at 10200.26,7230 h60
  text "Copper" at 11130,7230 h60
  text "1.40mil" at 11989.77,7230 h60
  text "6" at 9790.34,7110 h60
  text "Bottom Solder" at 10200.26,7110 h60
  text "Solder Resist" at 11130,7110 h60
  text "0.40mil" at 11989.77,7110 h60
  text "3.5" at 12639.6,7110 h60
  text "7" at 9790.34,6990 h60
  text "Bottom Overlay" at 10200.26,6990 h60
  text ".Layer_Name" at 577,-858.49 h60
M13 Component Bodies Top:
  text ".Layer_Name" at 577,-858.49 h60
M14 Component Bodies Bottom:
  text ".Layer_Name" at 577,-858.49 h60
M15 Courtyards Top:
  text ".Layer_Name" at 577,-858.49 h60
M16 Courtyards Bottom:
  text ".Layer_Name" at 577,-858.49 h60
Drill Drawing:
  text ".Layer_Name" at 577,-858.49 h60
M17 Embedded Cavity:
  text ".Layer_Name" at 577,-858.49 h60
M18 Embedded Assembly:
  text ".Layer_Name" at 577,-858.49 h60
M19 Embedded Keepout:
  text ".Layer_Name" at 577,-858.49 h60

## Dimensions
0,0 to 2300,0 on M2 Board Dimensions
0,0 to 0,1400 on M2 Board Dimensions
0,-400 to 1000,-400 on M2 Board Dimensions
